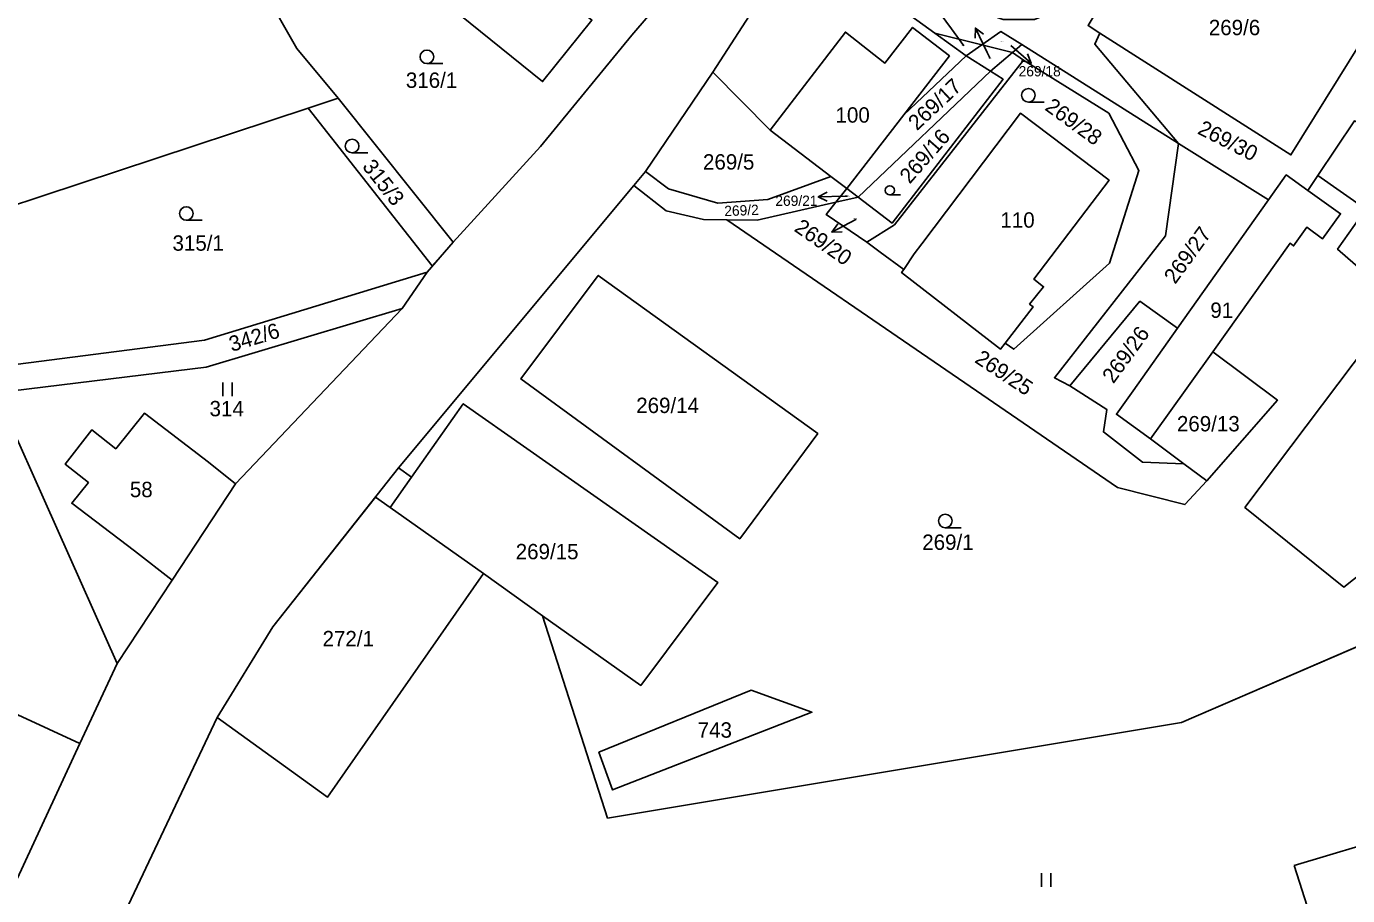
# Model space of a CAD drawing. Extents: x -590606 to -587796, y -1065936 to -1062515.
# Drawn here: x -589191 to -589044.8, y -1064624.7 to -1064528.5 of the extents above; entities that cross this region are included whole.
import ezdxf

# ---------------------------------------------------------------- set-up
doc = ezdxf.new("R2010")
doc.units = 0
for name, color, linetype in [('Parcela nároku', 7, 'Continuous'), ('Parcelní číslo', 7, 'Continuous'), ('Tok', 7, 'Continuous'), ('Vnější obvod_ Studené', 7, 'Continuous'), ('Vrstva 30', 7, 'Continuous')]:
    doc.layers.add(name, color=color, linetype=linetype)

msp = doc.modelspace()

# ---------------------------------------------------------------- linework, layer by layer
at = {"layer": 'Parcela nároku'}
for points in [[(-589232.4, -1064471.45), (-589208.79, -1064446.47), (-589168.83, -1064517.27), (-589164.65, -1064524.67), (-589161.07, -1064530.98), (-589156.51, -1064536.45), (-589159.83, -1064537.55), (-589201.82, -1064551.44)], [(-589076.57, -1064526.63), (-589079.42, -1064527.74), (-589082.89, -1064527.75), (-589090.91, -1064524.94), (-589100.01, -1064522.33), (-589090.45, -1064529.26), (-589085.24, -1064530.57), (-589083.14, -1064529.09), (-589080.83, -1064530.54), (-589063.47, -1064541.46), (-589072.75, -1064530.48), (-589072.17, -1064529.26), (-589073.49, -1064528.42), (-589065, -1064514.23), (-589051.15, -1064486.78), (-589048.73, -1064480.06), (-589048.6, -1064475.49), (-589049.2, -1064472.55), (-589049.53, -1064473.18), (-589052.72, -1064479.3), (-589054.06, -1064483.94), (-589057.13, -1064491.06), (-589069.47, -1064514.03)], [(-589073.49, -1064528.42), (-589065, -1064514.23), (-589059.07, -1064516.43), (-589059.42, -1064516.96), (-589052.04, -1064521.86), (-589051.51, -1064521.07), (-589050.55, -1064521.72), (-589046.57, -1064515.81), (-589047.52, -1064515.17), (-589046.98, -1064514.36), (-589054.41, -1064509.35), (-589056.13, -1064508.19), (-589058.63, -1064512.18), (-589062.32, -1064509.54), (-589058.39, -1064502.47), (-589035.51, -1064517.76), (-589051.04, -1064542.74), (-589072.17, -1064529.26)], [(-589129.44, -1064522.36), (-589131.76, -1064525.09), (-589128.4, -1064527.82), (-589133.87, -1064534.63), (-589146.45, -1064524.44), (-589140.87, -1064517.69), (-589136.06, -1064521.6), (-589134, -1064519.2), (-589146.94, -1064510.23), (-589164.65, -1064524.67), (-589161.07, -1064530.98), (-589156.51, -1064536.45), (-589143.75, -1064552.4), (-589134.1, -1064541.79), (-589130.39, -1064537.32), (-589123.98, -1064529.48), (-589122.18, -1064527.39)], [(-589131.76, -1064525.09), (-589128.4, -1064527.82), (-589133.87, -1064534.63), (-589146.45, -1064524.44), (-589140.87, -1064517.69), (-589136.06, -1064521.6), (-589134, -1064519.2), (-589133.61, -1064518.69), (-589129.31, -1064522.2), (-589129.44, -1064522.36)], [(-589105.28, -1064518.51), (-589100.01, -1064522.33), (-589090.45, -1064529.26), (-589086.97, -1064531.78), (-589093.87, -1064538.29), (-589088.84, -1064531.79), (-589092.91, -1064528.64), (-589095.97, -1064532.57), (-589100.35, -1064529.15), (-589108.67, -1064540.01), (-589115.01, -1064533.6)], [(-589092.91, -1064528.64), (-589088.84, -1064531.79), (-589093.87, -1064538.29), (-589100.2, -1064546.46), (-589101.96, -1064545.12), (-589108.67, -1064540.01), (-589100.35, -1064529.15), (-589095.97, -1064532.57)], [(-589090.45, -1064529.26), (-589085.24, -1064530.57), (-589086.97, -1064531.78)], [(-589080.83, -1064530.54), (-589083.14, -1064529.09), (-589085.24, -1064530.57), (-589081.85, -1064531.42)], [(-589071.78, -1064573.39), (-589067.46, -1064576.73), (-589062.88, -1064576.92), (-589060.35, -1064578.8), (-589062.76, -1064581.42), (-589070.22, -1064579.53), (-589087.84, -1064567.48), (-589113.48, -1064549.93), (-589110.12, -1064549.96), (-589101.41, -1064547.97), (-589102.49, -1064549.32), (-589097.97, -1064552.38), (-589096.5, -1064553.49), (-589093.88, -1064555.4), (-589094.12, -1064555.75), (-589083.18, -1064564.24), (-589082.66, -1064563.56), (-589081.72, -1064564.24), (-589071.12, -1064554.7), (-589067.85, -1064544.47), (-589071.17, -1064538.12), (-589080.64, -1064532.24), (-589081.85, -1064531.42), (-589080.83, -1064530.54), (-589063.47, -1064541.46), (-589064.9, -1064551.71), (-589077.21, -1064567.39), (-589075.49, -1064568.29), (-589071.42, -1064570.89)], [(-589085.24, -1064530.57), (-589086.97, -1064531.78), (-589084.27, -1064533.49), (-589081.85, -1064531.42)], [(-589101.41, -1064547.97), (-589098.95, -1064547.41), (-589095.17, -1064550.29), (-589082.89, -1064534.37), (-589084.27, -1064533.49), (-589081.85, -1064531.42), (-589080.64, -1064532.24), (-589094.9, -1064550.46), (-589097.97, -1064552.38), (-589102.49, -1064549.32)], [(-589093.87, -1064538.29), (-589086.97, -1064531.78), (-589084.27, -1064533.49), (-589098.95, -1064547.41), (-589100.2, -1064546.46)], [(-589108.67, -1064540.01), (-589115.01, -1064533.6), (-589122.47, -1064544.56), (-589119.91, -1064546.5), (-589114.45, -1064548.07), (-589108.92, -1064547.67), (-589101.96, -1064545.12)], [(-589098.95, -1064547.41), (-589084.27, -1064533.49), (-589082.89, -1064534.37), (-589095.17, -1064550.29)], [(-589067.85, -1064544.47), (-589071.17, -1064538.12), (-589080.64, -1064532.24), (-589094.9, -1064550.46), (-589097.97, -1064552.38), (-589096.5, -1064553.49), (-589093.88, -1064555.4), (-589092.73, -1064553.69), (-589091.88, -1064552.57), (-589080.98, -1064538.12), (-589071.15, -1064545.54), (-589079.5, -1064556.48), (-589078.4, -1064557.32), (-589079.95, -1064559.25), (-589079.57, -1064559.54), (-589082.66, -1064563.56), (-589081.72, -1064564.24), (-589071.12, -1064554.7)], [(-589159.83, -1064537.55), (-589156.51, -1064536.45), (-589143.75, -1064552.4), (-589146.1, -1064555.02)], [(-589201.82, -1064551.44), (-589159.83, -1064537.55), (-589146.1, -1064555.02), (-589143.75, -1064552.4), (-589146.65, -1064555.73), (-589171.28, -1064563.22), (-589195.69, -1064566.38)], [(-589091.88, -1064552.57), (-589080.98, -1064538.12), (-589071.15, -1064545.54), (-589079.5, -1064556.48), (-589078.4, -1064557.32), (-589079.95, -1064559.25), (-589079.57, -1064559.54), (-589082.66, -1064563.56), (-589083.18, -1064564.24), (-589094.12, -1064555.75), (-589093.88, -1064555.4), (-589092.73, -1064553.69)], [(-589048.04, -1064545), (-589043.98, -1064538.95), (-589010.14, -1064556.67), (-589018.54, -1064566.04), (-589029.13, -1064577.85), (-589045.18, -1064590.56), (-589056.12, -1064581.74), (-589039.04, -1064559.11), (-589045.87, -1064553.17), (-589042.74, -1064548.76)], [(-589053.52, -1064547.72), (-589063.47, -1064541.46), (-589064.9, -1064551.71), (-589077.21, -1064567.39), (-589075.49, -1064568.29), (-589067.74, -1064558.93), (-589063.6, -1064561.92)], [(-589123.77, -1064546.13), (-589122.47, -1064544.56), (-589119.91, -1064546.5), (-589114.45, -1064548.07), (-589108.92, -1064547.67), (-589101.96, -1064545.12), (-589100.2, -1064546.46), (-589101.41, -1064547.97), (-589110.12, -1064549.96), (-589113.48, -1064549.93), (-589116.05, -1064549.9), (-589120.17, -1064548.91)], [(-589070.35, -1064571.44), (-589068.5, -1064568.83), (-589063.6, -1064561.92), (-589053.52, -1064547.72), (-589051.55, -1064544.95), (-589049.16, -1064546.66), (-589045.54, -1064549.24), (-589047.52, -1064552.02), (-589049.28, -1064550.75), (-589050.74, -1064552.8), (-589051.13, -1064552.52), (-589059.69, -1064564.53), (-589064.71, -1064571.53), (-589066.59, -1064574.16)], [(-589101.41, -1064547.97), (-589100.2, -1064546.46), (-589098.95, -1064547.41)], [(-589171.28, -1064563.22), (-589146.65, -1064555.73), (-589149.4, -1064559.72), (-589171.12, -1064566.23), (-589194.33, -1064569.05), (-589195.69, -1064566.38)], [(-589103.41, -1064573.57), (-589112.04, -1064585.2), (-589136.26, -1064567.52), (-589127.71, -1064556.08)], [(-589136.26, -1064567.52), (-589127.71, -1064556.08), (-589103.41, -1064573.57), (-589112.04, -1064585.2)], [(-589171.12, -1064566.23), (-589149.4, -1064559.72), (-589167.86, -1064579.14), (-589170.85, -1064576.72), (-589177.93, -1064571.33), (-589181.12, -1064575.26), (-589183.77, -1064573.16), (-589186.71, -1064576.96), (-589184.14, -1064578.99), (-589185.99, -1064581.28), (-589179.04, -1064586.54), (-589174.88, -1064589.8), (-589180.97, -1064599.01), (-589194.33, -1064569.05)], [(-589062.88, -1064576.92), (-589066.59, -1064574.16), (-589070.35, -1064571.44), (-589068.5, -1064568.83), (-589063.6, -1064561.92), (-589067.74, -1064558.93), (-589075.49, -1064568.29), (-589071.42, -1064570.89), (-589071.78, -1064573.39), (-589067.46, -1064576.73)], [(-589064.71, -1064571.53), (-589066.59, -1064574.16), (-589062.88, -1064576.92), (-589060.35, -1064578.8), (-589052.52, -1064569.88), (-589059.69, -1064564.53)], [(-589194.33, -1064569.05), (-589180.97, -1064599.01), (-589185.08, -1064607.88), (-589191.95, -1064604.69), (-589196.61, -1064614.26), (-589199.45, -1064612.86), (-589202.15, -1064618.39), (-589192.01, -1064622.83), (-589193.83, -1064626.75), (-589206.34, -1064664.38), (-589210.5, -1064654.09), (-589244.72, -1064570.89), (-589218.91, -1064568.78)], [(-589170.85, -1064576.72), (-589167.86, -1064579.14), (-589174.88, -1064589.8), (-589179.04, -1064586.54), (-589185.99, -1064581.28), (-589184.14, -1064578.99), (-589186.71, -1064576.96), (-589183.77, -1064573.16), (-589181.12, -1064575.26), (-589177.93, -1064571.33)], [(-589148.37, -1064578.39), (-589150.74, -1064581.74), (-589140.42, -1064589.07), (-589133.86, -1064593.72), (-589123, -1064601.43), (-589114.46, -1064590.06), (-589142.64, -1064570.28)], [(-589150.74, -1064581.74), (-589140.42, -1064589.07), (-589157.66, -1064613.8), (-589169.88, -1064604.99), (-589163.72, -1064594.94), (-589149.8, -1064577.36), (-589148.37, -1064578.39)], [(-589126.11, -1064613), (-589104.06, -1064604.41), (-589110.77, -1064601.97), (-589127.63, -1064608.83)], [(-589110.77, -1064601.97), (-589104.06, -1064604.41), (-589126.11, -1064613), (-589127.63, -1064608.83)], [(-589202.15, -1064618.39), (-589199.45, -1064612.86), (-589196.61, -1064614.26), (-589191.95, -1064604.69), (-589185.08, -1064607.88), (-589192.01, -1064622.83)]]:
    msp.add_lwpolyline(points, close=True, dxfattribs=at)
for points in [[(-589219.53, -1064748.72), (-589186.36, -1064642.57), (-589183.62, -1064634.01), (-589183.45, -1064633.66), (-589181.35, -1064629.23), (-589179.39, -1064625.08), (-589169.88, -1064604.99), (-589163.72, -1064594.94), (-589149.8, -1064577.36), (-589123.77, -1064546.13), (-589122.47, -1064544.56), (-589115.01, -1064533.6), (-589105.28, -1064518.51), (-589092.65, -1064498.9), (-589083.82, -1064476.76), (-589078.44, -1064456.79), (-589078.02, -1064448.81)], [(-589088.39, -1064454.14), (-589094.76, -1064474.31), (-589102.2, -1064492.78), (-589122.18, -1064527.39), (-589123.98, -1064529.48), (-589130.39, -1064537.32), (-589134.1, -1064541.79), (-589143.75, -1064552.4), (-589146.65, -1064555.73), (-589149.4, -1064559.72), (-589167.86, -1064579.14), (-589174.88, -1064589.8), (-589180.97, -1064599.01), (-589185.08, -1064607.88), (-589192.01, -1064622.83)], [(-589043.98, -1064538.95), (-589048.04, -1064545), (-589049.16, -1064546.66), (-589051.55, -1064544.95), (-589053.52, -1064547.72), (-589063.47, -1064541.46), (-589072.75, -1064530.48), (-589072.17, -1064529.26), (-589051.04, -1064542.74), (-589035.51, -1064517.76)], [(-589036.79, -1064594.17), (-589063.15, -1064605.55), (-589126.67, -1064616.12), (-589133.86, -1064593.72), (-589123, -1064601.43), (-589114.46, -1064590.06), (-589142.64, -1064570.28), (-589148.37, -1064578.39), (-589149.8, -1064577.36), (-589123.77, -1064546.13), (-589120.17, -1064548.91), (-589116.05, -1064549.9), (-589113.48, -1064549.93), (-589087.84, -1064567.48), (-589070.22, -1064579.53), (-589062.76, -1064581.42), (-589060.35, -1064578.8), (-589052.52, -1064569.88), (-589059.69, -1064564.53), (-589051.13, -1064552.52), (-589050.74, -1064552.8), (-589049.28, -1064550.75), (-589047.52, -1064552.02), (-589045.54, -1064549.24), (-589049.16, -1064546.66), (-589048.04, -1064545), (-589042.74, -1064548.76), (-589045.87, -1064553.17), (-589039.04, -1064559.11), (-589056.12, -1064581.74), (-589045.18, -1064590.56), (-589029.13, -1064577.85)], [(-589179.39, -1064625.08), (-589169.88, -1064604.99), (-589157.66, -1064613.8), (-589140.42, -1064589.07), (-589133.86, -1064593.72), (-589126.67, -1064616.12), (-589063.15, -1064605.55), (-589036.79, -1064594.17), (-589019.52, -1064582.82), (-589010.33, -1064570.28), (-589009.13, -1064570.9), (-589004.37, -1064563.21), (-588995.65, -1064568.41), (-588997.54, -1064571.27), (-589018.59, -1064595.36), (-589018.06, -1064634.7)]]:
    msp.add_lwpolyline(points, dxfattribs=at)
at = {"layer": 'Parcelní číslo'}
for p, q in [((-589088.61, -1064528.8), (-589090.39, -1064526.38)), ((-589087.25, -1064530.66), (-589088.61, -1064528.8)), ((-589084.65, -1064531.41), (-589085.96, -1064528.71)), ((-589082.03, -1064530.62), (-589079.77, -1064532.59)), ((-589084.33, -1064532.07), (-589084.65, -1064531.41)), ((-589100.36, -1064547.32), (-589103.36, -1064547.38)), ((-589100.1, -1064547.31), (-589100.36, -1064547.32)), ((-589099.19, -1064549.88), (-589101.84, -1064551.29)), ((-589099.14, -1064549.86), (-589099.19, -1064549.88))]:
    msp.add_line(p, q, dxfattribs=at)
for points in [[(-589085.97, -1064529.83), (-589085.96, -1064528.71), (-589085.07, -1064529.39)], [(-589080.19, -1064531.56), (-589079.77, -1064532.59), (-589080.85, -1064532.31)], [(-589102.35, -1064547.86), (-589103.36, -1064547.38), (-589102.37, -1064546.86)], [(-589100.72, -1064551.26), (-589101.84, -1064551.29), (-589101.19, -1064550.38)]]:
    msp.add_lwpolyline(points, dxfattribs=at)
at = {"layer": 'Tok'}
msp.add_lwpolyline([(-589050.66, -1064621.38), (-589039.58, -1064618.05), (-589032.2, -1064642.61), (-589042.85, -1064645.81)], close=True, dxfattribs=at)
at = {"layer": 'Vnější obvod_ Studené'}
for p, q in [((-589152.36, -1064580.6), (-589163.72, -1064594.94)), ((-589150.74, -1064581.74), (-589152.36, -1064580.6)), ((-589140.42, -1064589.07), (-589150.74, -1064581.74)), ((-589133.86, -1064593.72), (-589140.42, -1064589.07)), ((-589163.72, -1064594.94), (-589169.88, -1064604.99)), ((-589126.67, -1064616.12), (-589133.86, -1064593.72)), ((-589036.79, -1064594.17), (-589063.15, -1064605.55)), ((-589169.88, -1064604.99), (-589179.39, -1064625.08)), ((-589063.15, -1064605.55), (-589126.67, -1064616.12))]:
    msp.add_line(p, q, dxfattribs=at)
at = {"layer": 'Vrstva 30'}
for p, q in [((-589144.92, -1064532.64), (-589146.67, -1064532.64)), ((-589078.34, -1064536.89), (-589080.09, -1064536.89)), ((-589153.2, -1064542.51), (-589154.95, -1064542.51)), ((-589094.26, -1064547.16), (-589095.43, -1064547.16)), ((-589171.55, -1064549.97), (-589173.3, -1064549.97)), ((-589169.25, -1064567.92), (-589169.25, -1064569.42)), ((-589168.22, -1064569.42), (-589168.22, -1064567.92)), ((-589087.54, -1064583.99), (-589089.29, -1064583.99)), ((-589078.65, -1064622.22), (-589078.65, -1064623.72)), ((-589077.62, -1064623.72), (-589077.62, -1064622.22))]:
    msp.add_line(p, q, dxfattribs=at)
for centre, radius in [((-589146.67, -1064531.89), 0.75), ((-589080.09, -1064536.14), 0.75), ((-589154.95, -1064541.76), 0.75), ((-589095.43, -1064546.66), 0.503), ((-589173.3, -1064549.22), 0.75), ((-589089.29, -1064583.24), 0.75)]:
    msp.add_circle(centre, radius, dxfattribs=at)

# ---------------------------------------------------------------- texts
at = {"layer": 'Parcela nároku'}
for s, height, p in [('269/6', 1.7, (-589060.12, -1064529.49)), ('269/22', 0.1, (-589087.48, -1064530.66)), ('269/18', 0.1, (-589083.2, -1064530.26)), ('269/23', 0.1, (-589084.56, -1064532.07)), ('316/1', 1.7, (-589149, -1064535.32)), ('100', 1.7, (-589101.44, -1064539.17)), ('269/5', 1.7, (-589116.11, -1064544.36)), ('269/21', 0.1, (-589100.3, -1064547.31)), ('269/20', 0.1, (-589099.52, -1064549.82)), ('110', 1.7, (-589083.19, -1064550.79)), ('315/1', 1.7, (-589174.83, -1064553.34)), ('91', 1.7, (-589059.95, -1064560.77)), ('314', 1.7, (-589170.73, -1064571.66)), ('269/14', 1.7, (-589123.5, -1064571.3)), ('269/13', 1.7, (-589063.65, -1064573.33)), ('58', 1.7, (-589179.55, -1064580.61)), ('269/1', 1.7, (-589091.84, -1064586.44)), ('269/15', 1.7, (-589136.84, -1064587.48)), ('272/1', 1.7, (-589158.22, -1064597.11)), ('743', 1.7, (-589116.7, -1064607.22))]:
    msp.add_text(s, height=height, dxfattribs=at).set_placement(p)
for s, height, rotation, p in [('269/17', 1.7, 43.0664, (-589092.42, -1064540.12)), ('269/28', 1.7, 324, (-589078.37, -1064537.69)), ('269/30', 1.7, 333, (-589061.47, -1064540.34)), ('269/16', 1.7, 48.6455, (-589093.23, -1064546.03)), ('315/3', 1.7, 308.2199, (-589153.9, -1064544.06)), ('269/2', 1.14, 2.2283, (-589113.73, -1064549.52)), ('269/27', 1.7, 54, (-589063.84, -1064557.12)), ('342/6', 1.7, 16.6847, (-589168.27, -1064564.54)), ('269/26', 1.7, 54, (-589070.68, -1064568.13)), ('269/25', 1.7, 326.5523, (-589086.14, -1064565.62))]:
    msp.add_text(s, height=height, rotation=rotation, dxfattribs=at).set_placement(p)
at = {"layer": 'Parcelní číslo'}
for s, p in [('269/18', (-589081.17, -1064534.05)), ('269/21', (-589108.1, -1064548.38))]:
    msp.add_text(s, height=1.14, dxfattribs=at).set_placement(p)
msp.add_text('269/20', height=1.7, rotation=325.0514, dxfattribs=at).set_placement((-589106.12, -1064551.09))

doc.saveas('drawing.dxf')
